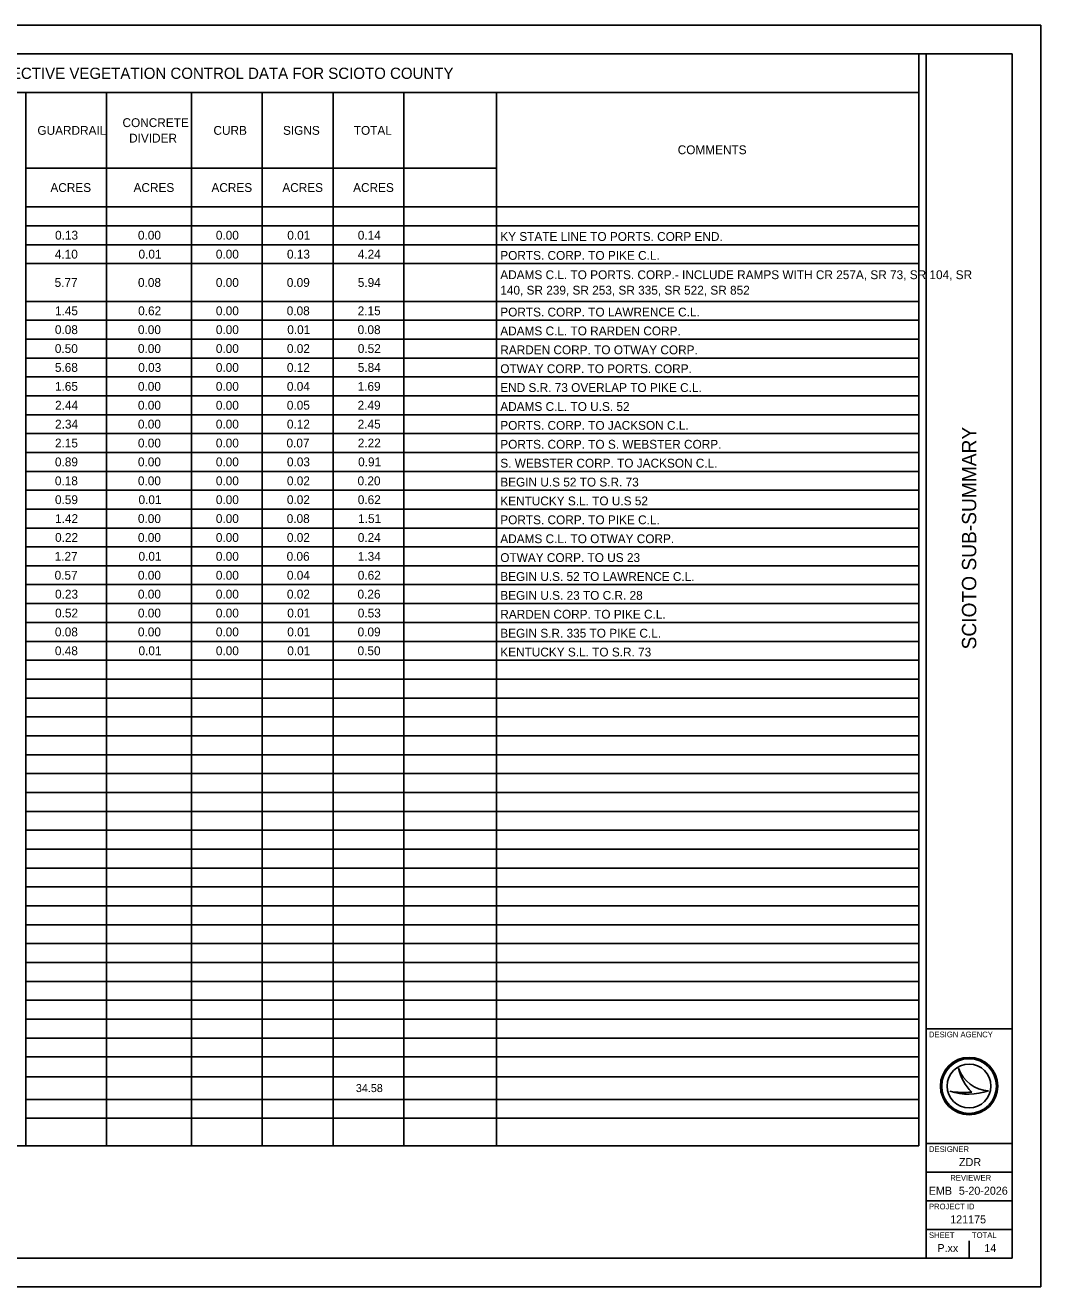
# Model space of a CAD drawing. Extents: x 0 to 34, y 0 to 22.
# Drawn here: x 16.29 to 34, y 0 to 22 of the extents above; entities that cross this region are included whole.
import ezdxf

# ---------------------------------------------------------------- set-up
doc = ezdxf.new("R2010")
doc.units = 0
for name, color, linetype in [('SH_Border', 7, 'Continuous'), ('SH_Cut_Line', 7, 'Continuous'), ('SH_Data', 7, 'Continuous'), ('SH_Text', 7, 'Continuous')]:
    doc.layers.add(name, color=color, linetype=linetype)

msp = doc.modelspace()

# ---------------------------------------------------------------- linework, layer by layer
at = {"layer": 'SH_Border'}
for p, q in [((32, 0.5), (32, 21.5)), ((32, 4.5), (33.5, 4.5)), ((32, 2.5), (33.5, 2.5)), ((32, 2), (33.5, 2)), ((32, 1.5), (33.5, 1.5)), ((32, 1), (33.5, 1))]:
    msp.add_line(p, q, dxfattribs=at)
msp.add_lwpolyline([(1.5, 21.5), (33.5, 21.5), (33.5, 0.5), (1.5, 0.5)], close=True, dxfattribs=at)
at = {"layer": 'SH_Cut_Line'}
msp.add_lwpolyline([(0, 0), (34, 0), (34, 22), (0, 22)], close=True, dxfattribs=at)
at = {"layer": 'SH_Data'}
for p, q in [((32.567, 3.81), (32.567, 3.81)), ((32.417, 3.41), (32.417, 3.41)), ((32.75, 3.5), (32.75, 3.5)), ((33.087, 3.419), (33.087, 3.419)), ((32.375, 0.675), (32.375, 0.675)), ((32.75, 0.5), (32.75, 0.8))]:
    msp.add_line(p, q, dxfattribs=at)
for radius in [0.5, 0.477, 0.477, 0.382]:
    msp.add_circle((32.75, 3.5), radius, dxfattribs=at)
for centre, radius, start, end in [((33.116, 3.998), 0.58, 198.9257, 198.9319), ((33.347, 3.97), 0.796, 191.6379, 191.6421), ((33.116, 3.998), 0.58, 198.9319, 267.1657), ((33.347, 3.97), 0.796, 191.6421, 226.0947), ((32.739, 4.37), 1.013, 251.4576, 290.0832), ((32.648, 4.654), 1.266, 259.4964, 259.4995), ((32.739, 4.37), 1.013, 251.4527, 251.4576), ((32.648, 4.654), 1.266, 259.4995, 276.6672)]:
    msp.add_arc(centre, radius, start, end, dxfattribs=at)
at = {"layer": 'SH_Text'}
for p, q in [((1.5, 21.5), (31.872, 21.5)), ((31.872, 21.5), (31.872, 2.46)), ((7.451, 20.825), (16.302, 20.825)), ((16.28, 20.825), (31.872, 20.825)), ((16.302, 20.825), (16.302, 2.46)), ((17.707, 20.825), (17.707, 2.46)), ((19.189, 20.825), (19.189, 2.46)), ((20.425, 20.825), (20.425, 2.46)), ((21.66, 20.825), (21.66, 2.46)), ((22.895, 20.825), (22.895, 2.46)), ((24.509, 20.825), (24.509, 2.46)), ((16.302, 19.507), (24.509, 19.507)), ((16.302, 18.832), (31.872, 18.832)), ((16.302, 18.502), (31.872, 18.502)), ((16.302, 18.173), (31.872, 18.173)), ((16.302, 17.844), (31.872, 17.844)), ((16.302, 17.185), (31.872, 17.185)), ((16.302, 16.855), (31.872, 16.855)), ((16.302, 16.526), (31.872, 16.526)), ((16.302, 16.196), (31.872, 16.196)), ((16.302, 15.867), (31.872, 15.867)), ((16.302, 15.538), (31.872, 15.538)), ((16.302, 15.208), (31.872, 15.208)), ((16.302, 14.879), (31.872, 14.879)), ((16.302, 14.549), (31.872, 14.549)), ((16.302, 14.22), (31.872, 14.22)), ((16.302, 13.891), (31.872, 13.891)), ((16.302, 13.561), (31.872, 13.561)), ((16.302, 13.232), (31.872, 13.232)), ((16.302, 12.902), (31.872, 12.902)), ((16.302, 12.573), (31.872, 12.573)), ((16.302, 12.244), (31.872, 12.244)), ((16.302, 11.914), (31.872, 11.914)), ((16.302, 11.585), (31.872, 11.585)), ((16.302, 11.255), (31.872, 11.255)), ((16.302, 10.926), (31.872, 10.926)), ((16.302, 10.596), (31.872, 10.596)), ((16.302, 10.267), (31.872, 10.267)), ((16.302, 9.938), (31.872, 9.938)), ((16.302, 9.608), (31.872, 9.608)), ((16.302, 9.279), (31.872, 9.279)), ((16.302, 8.949), (31.872, 8.949)), ((16.302, 8.62), (31.872, 8.62)), ((16.302, 8.291), (31.872, 8.291)), ((16.302, 7.961), (31.872, 7.961)), ((16.302, 7.632), (31.872, 7.632)), ((16.302, 7.302), (31.872, 7.302)), ((16.302, 6.973), (31.872, 6.973)), ((16.302, 6.644), (31.872, 6.644)), ((16.302, 6.314), (31.872, 6.314)), ((16.302, 5.985), (31.872, 5.985)), ((16.302, 5.655), (31.872, 5.655)), ((16.302, 5.326), (31.872, 5.326)), ((16.302, 4.996), (31.872, 4.996)), ((16.302, 4.667), (31.872, 4.667)), ((16.302, 4.338), (31.872, 4.338)), ((16.302, 4.008), (31.872, 4.008)), ((16.302, 3.662), (31.872, 3.662)), ((16.302, 3.267), (31.872, 3.267)), ((16.302, 2.938), (31.872, 2.938)), ((7.451, 2.46), (16.302, 2.46)), ((16.28, 2.46), (31.872, 2.46))]:
    msp.add_line(p, q, dxfattribs=at)

# ---------------------------------------------------------------- texts
at = {"layer": 'SH_Data'}
msp.add_text('SCIOTO SUB-SUMMARY', height=0.25, rotation=90, dxfattribs=at).set_placement((32.875, 11.115))
for s, height, p in [('DESIGN AGENCY', 0.1, (32.05, 4.35)), ('DESIGNER', 0.1, (32.05, 2.35)), ('ZDR', 0.14, (32.575, 2.105)), ('REVIEWER', 0.1, (32.422, 1.85)), ('EMB', 0.14, (32.047, 1.605)), ('5-20-2026', 0.14, (32.571, 1.605)), ('PROJECT ID', 0.1, (32.05, 1.35)), ('121175', 0.14, (32.421, 1.105)), ('SHEET', 0.1, (32.05, 0.85)), ('TOTAL', 0.1, (32.8, 0.85)), ('P.xx', 0.14, (32.197, 0.605)), ('14', 0.14, (33.016, 0.605))]:
    msp.add_text(s, height=height, dxfattribs=at).set_placement(p)
at = {"layer": 'SH_Text'}
for s, height, p in [('HERBICIDAL SPRAYING NONSELECTIVE VEGETATION CONTROL DATA FOR SCIOTO COUNTY', 0.196, (11.89, 21.064)), ('GUARDRAIL', 0.154, (16.503, 20.089)), ('CONCRETE', 0.154, (17.987, 20.224)), ('CURB', 0.154, (19.573, 20.089)), ('SIGNS', 0.154, (20.786, 20.089)), ('TOTAL', 0.154, (22.02, 20.089)), ('DIVIDER', 0.154, (18.102, 19.954)), ('COMMENTS', 0.154, (27.669, 19.751)), ('ACRES', 0.154, (16.73, 19.092)), ('ACRES', 0.154, (18.18, 19.092)), ('ACRES', 0.154, (19.538, 19.092)), ('ACRES', 0.154, (20.774, 19.092)), ('ACRES', 0.154, (22.009, 19.092)), ('0.13', 0.154, (16.811, 18.261)), ('0.00', 0.154, (18.256, 18.261)), ('0.00', 0.154, (19.615, 18.261)), ('0.01', 0.154, (20.86, 18.261)), ('0.14', 0.154, (22.09, 18.261)), ('KY STATE LINE TO PORTS. CORP END.', 0.154, (24.575, 18.239)), ('4.10', 0.154, (16.807, 17.931)), ('0.01', 0.154, (18.266, 17.931)), ('0.00', 0.154, (19.615, 17.931)), ('0.13', 0.154, (20.855, 17.931)), ('4.24', 0.154, (22.09, 17.931)), ('PORTS. CORP. TO PIKE C.L.', 0.154, (24.575, 17.909)), ('ADAMS C.L. TO PORTS. CORP.- INCLUDE RAMPS WITH CR 257A, SR 73, SR 104, SR ', 0.154, (24.575, 17.572)), ('5.77', 0.154, (16.803, 17.437)), ('0.08', 0.154, (18.257, 17.437)), ('0.00', 0.154, (19.615, 17.437)), ('0.09', 0.154, (20.852, 17.437)), ('5.94', 0.154, (22.09, 17.437)), ('140, SR 239, SR 253, SR 335, SR 522, SR 852', 0.154, (24.575, 17.302)), ('1.45', 0.154, (16.809, 16.943)), ('0.62', 0.154, (18.26, 16.943)), ('0.00', 0.154, (19.615, 16.943)), ('0.08', 0.154, (20.851, 16.943)), ('2.15', 0.154, (22.088, 16.943)), ('PORTS. CORP. TO LAWRENCE C.L.', 0.154, (24.575, 16.921)), ('0.08', 0.154, (16.808, 16.614)), ('0.00', 0.154, (18.256, 16.614)), ('0.00', 0.154, (19.615, 16.614)), ('0.01', 0.154, (20.86, 16.614)), ('0.08', 0.154, (22.087, 16.614)), ('ADAMS C.L. TO RARDEN CORP.', 0.154, (24.575, 16.592)), ('0.50', 0.154, (16.807, 16.284)), ('0.00', 0.154, (18.256, 16.284)), ('0.00', 0.154, (19.615, 16.284)), ('0.02', 0.154, (20.854, 16.284)), ('0.52', 0.154, (22.09, 16.284)), ('RARDEN CORP. TO OTWAY CORP.', 0.154, (24.575, 16.262)), ('5.68', 0.154, (16.808, 15.955)), ('0.03', 0.154, (18.261, 15.955)), ('0.00', 0.154, (19.615, 15.955)), ('0.12', 0.154, (20.854, 15.955)), ('5.84', 0.154, (22.09, 15.955)), ('OTWAY CORP. TO PORTS. CORP.', 0.154, (24.575, 15.933)), ('1.65', 0.154, (16.809, 15.625)), ('0.00', 0.154, (18.256, 15.625)), ('0.00', 0.154, (19.615, 15.625)), ('0.04', 0.154, (20.854, 15.625)), ('1.69', 0.154, (22.087, 15.625)), ('END S.R. 73 OVERLAP TO PIKE C.L.', 0.154, (24.575, 15.604)), ('2.44', 0.154, (16.811, 15.296)), ('0.00', 0.154, (18.256, 15.296)), ('0.00', 0.154, (19.615, 15.296)), ('0.05', 0.154, (20.853, 15.296)), ('2.49', 0.154, (22.087, 15.296)), ('ADAMS C.L. TO U.S. 52', 0.154, (24.575, 15.274)), ('2.34', 0.154, (16.811, 14.967)), ('0.00', 0.154, (18.256, 14.967)), ('0.00', 0.154, (19.615, 14.967)), ('0.12', 0.154, (20.854, 14.967)), ('2.45', 0.154, (22.088, 14.967)), ('PORTS. CORP. TO JACKSON C.L.', 0.154, (24.575, 14.945)), ('2.15', 0.154, (16.809, 14.637)), ('0.00', 0.154, (18.256, 14.637)), ('0.00', 0.154, (19.615, 14.637)), ('0.07', 0.154, (20.847, 14.637)), ('2.22', 0.154, (22.09, 14.637)), ('PORTS. CORP. TO S. WEBSTER CORP.', 0.154, (24.575, 14.615)), ('0.89', 0.154, (16.809, 14.308)), ('0.00', 0.154, (18.256, 14.308)), ('0.00', 0.154, (19.615, 14.308)), ('0.03', 0.154, (20.855, 14.308)), ('0.91', 0.154, (22.096, 14.308)), ('S. WEBSTER CORP. TO JACKSON C.L.', 0.154, (24.575, 14.286)), ('0.18', 0.154, (16.808, 13.978)), ('0.00', 0.154, (18.256, 13.978)), ('0.00', 0.154, (19.615, 13.978)), ('0.02', 0.154, (20.854, 13.978)), ('0.20', 0.154, (22.086, 13.978)), ('BEGIN U.S 52 TO S.R. 73', 0.154, (24.575, 13.956)), ('0.59', 0.154, (16.809, 13.649)), ('0.01', 0.154, (18.266, 13.649)), ('0.00', 0.154, (19.615, 13.649)), ('0.02', 0.154, (20.854, 13.649)), ('0.62', 0.154, (22.09, 13.649)), ('KENTUCKY S.L. TO U.S 52', 0.154, (24.575, 13.627)), ('1.42', 0.154, (16.811, 13.319)), ('0.00', 0.154, (18.256, 13.319)), ('0.00', 0.154, (19.615, 13.319)), ('0.08', 0.154, (20.851, 13.319)), ('1.51', 0.154, (22.096, 13.319)), ('PORTS. CORP. TO PIKE C.L.', 0.154, (24.575, 13.298)), ('0.22', 0.154, (16.811, 12.99)), ('0.00', 0.154, (18.256, 12.99)), ('0.00', 0.154, (19.615, 12.99)), ('0.02', 0.154, (20.854, 12.99)), ('0.24', 0.154, (22.09, 12.99)), ('ADAMS C.L. TO OTWAY CORP.', 0.154, (24.575, 12.968)), ('1.27', 0.154, (16.803, 12.661)), ('0.01', 0.154, (18.266, 12.661)), ('0.00', 0.154, (19.615, 12.661)), ('0.06', 0.154, (20.849, 12.661)), ('1.34', 0.154, (22.09, 12.661)), ('OTWAY CORP. TO US 23', 0.154, (24.575, 12.639)), ('0.57', 0.154, (16.803, 12.331)), ('0.00', 0.154, (18.256, 12.331)), ('0.00', 0.154, (19.615, 12.331)), ('0.04', 0.154, (20.854, 12.331)), ('0.62', 0.154, (22.09, 12.331)), ('BEGIN U.S. 52 TO LAWRENCE C.L.', 0.154, (24.575, 12.309)), ('0.23', 0.154, (16.811, 12.002)), ('0.00', 0.154, (18.256, 12.002)), ('0.00', 0.154, (19.615, 12.002)), ('0.02', 0.154, (20.854, 12.002)), ('0.26', 0.154, (22.085, 12.002)), ('BEGIN U.S. 23 TO C.R. 28', 0.154, (24.575, 11.98)), ('0.52', 0.154, (16.811, 11.672)), ('0.00', 0.154, (18.256, 11.672)), ('0.00', 0.154, (19.615, 11.672)), ('0.01', 0.154, (20.86, 11.672)), ('0.53', 0.154, (22.09, 11.672)), ('RARDEN CORP. TO PIKE C.L.', 0.154, (24.575, 11.651)), ('0.08', 0.154, (16.808, 11.343)), ('0.00', 0.154, (18.256, 11.343)), ('0.00', 0.154, (19.615, 11.343)), ('0.01', 0.154, (20.86, 11.343)), ('0.09', 0.154, (22.087, 11.343)), ('BEGIN S.R. 335 TO PIKE C.L.', 0.154, (24.575, 11.321)), ('0.48', 0.154, (16.808, 11.014)), ('0.01', 0.154, (18.266, 11.014)), ('0.00', 0.154, (19.615, 11.014)), ('0.01', 0.154, (20.86, 11.014)), ('0.50', 0.154, (22.086, 11.014)), ('KENTUCKY S.L. TO S.R. 73', 0.154, (24.575, 10.992)), ('34.58', 0.14, (22.057, 3.395))]:
    msp.add_text(s, height=height, dxfattribs=at).set_placement(p)

doc.saveas('drawing.dxf')
